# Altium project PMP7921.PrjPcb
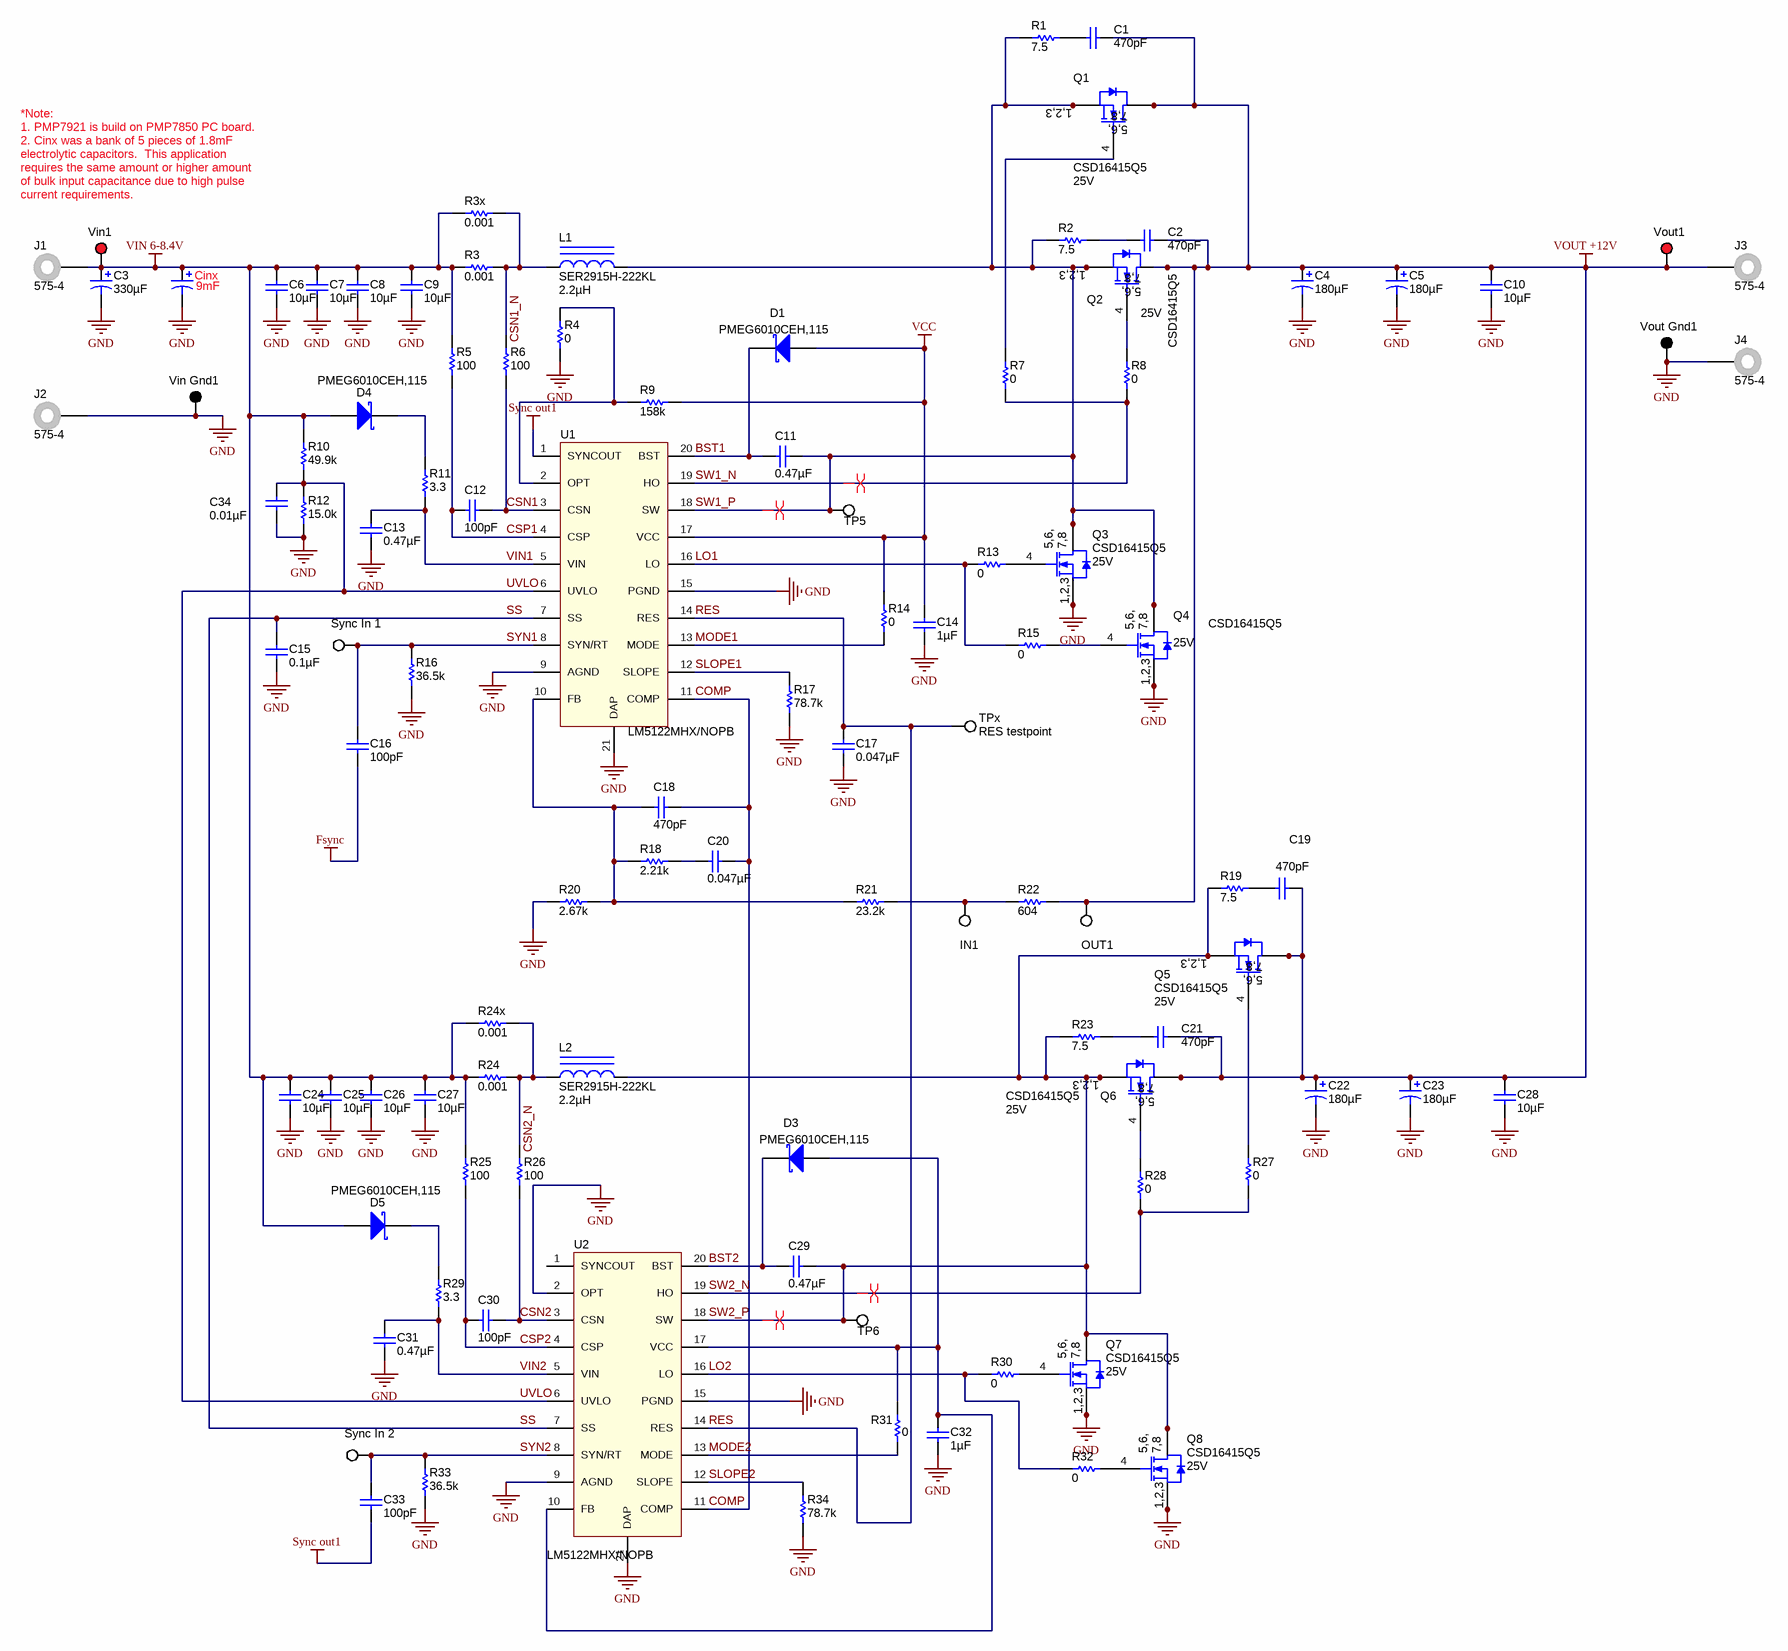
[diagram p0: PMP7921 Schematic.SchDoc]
TID: PMP7921; TechSupport: http://www.ti.com/support; SCH_Rev: 1; PRJ_Title: LM5122 Dual Phase Boost; PRJ_Number: PMP7921; PRJ_Engineer: Hrag Kasparian; PRJ_Customer: Public Release; PCB_Rev: B; PCB_Layout: Hrag Kasparian; EVM_Orderable: N/A; CopyrightYear: 2015
2 sheets, 110 parts. Net scope: global (net labels, ports and power ports of the same name join across sheets).
Board file: PMP7850 REVB.PcbDoc
Sheets:
  PMP7921 Schematic.SchDoc
  PMP7921_Hardware.SchDoc

## Sheet PMP7921 Schematic.SchDoc
size 558 x 431 mm; DocumentNumber: 1; SheetNumber: 1; SheetTotal: 2; PageSetup: Record=PageOptions¦CenterHorizontal=True¦CenterVertical=True¦PrintScale=0.70¦XCorrection=1.00¦YCorrection=1.00¦PrintKind=1¦BorderSize=5000000¦LeftOffset=0¦BottomOffset=0¦Orientation=2¦PaperLength=1000¦PaperWidth=1000¦Scale=100¦PaperSource=15¦PrintQuality=600¦MediaType=1¦DitherType=10¦PaperKind=11x17¦PrintScaleMode=1

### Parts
C1  ValueDisplayed: 470pF  [0805_HV]  (hidden comment: GRM2165C2A471JA01D)
C2  ValueDisplayed: 470pF  [0805_HV]  (hidden comment: GRM2165C2A471JA01D)
C3  ValueDisplayed: 330µF  [SVPS_F8]  (hidden comment: 10SVPS330M)
C4  ValueDisplayed: 180µF  [SVP_F8]  (hidden comment: 16SVP180MX)
C5  ValueDisplayed: 180µF  [SVP_F8]  (hidden comment: 16SVP180MX)
C6  ValueDisplayed: 10µF  [1206]  (hidden comment: C3216X5R1C106M)
C7  ValueDisplayed: 10µF  [1206]  (hidden comment: C3216X5R1C106M)
C8  ValueDisplayed: 10µF  [1206]  (hidden comment: C3216X5R1C106M)
C9  ValueDisplayed: 10µF  [1206]  (hidden comment: C3216X5R1C106M)
C10  ValueDisplayed: 10µF  [1206]  (hidden comment: C3216X5R1C106M)
C11  ValueDisplayed: 0.47µF  [0603_HV]  (hidden comment: GRM188R71E474KA12D)
C12  ValueDisplayed: 100pF  [0603_HV]  (hidden comment: GRM1885C1H101JA01D)
C13  ValueDisplayed: 0.47µF  [0603_HV]  (hidden comment: GRM188R71E474KA12D)
C14  ValueDisplayed: 1µF  [0603_HV]  (hidden comment: GRM188R71E105KA12D)
C15  ValueDisplayed: 0.1µF  [0603_HV]  (hidden comment: GRM188R71E104KA01D)
C16  ValueDisplayed: 100pF  [0603_HV]  (hidden comment: GRM1885C1H101JA01D)
C17  ValueDisplayed: 0.047µF  [0603_HV]  (hidden comment: GRM188R71E473KA01D)
C18  ValueDisplayed: 470pF  [0603]  (hidden comment: 06035A471JAT2A)
C19  ValueDisplayed: 470pF  [0805_HV]  (hidden comment: GRM2165C2A471JA01D)
C20  ValueDisplayed: 0.047µF  [0603]  (hidden comment: 06033C473JAT2A)
C21  ValueDisplayed: 470pF  [0805_HV]  (hidden comment: GRM2165C2A471JA01D)
C22  ValueDisplayed: 180µF  [SVP_F8]  (hidden comment: 16SVP180MX)
C23  ValueDisplayed: 180µF  [SVP_F8]  (hidden comment: 16SVP180MX)
C24  ValueDisplayed: 10µF  [1206]  (hidden comment: C3216X5R1C106M)
C25  ValueDisplayed: 10µF  [1206]  (hidden comment: C3216X5R1C106M)
C26  ValueDisplayed: 10µF  [1206]  (hidden comment: C3216X5R1C106M)
C27  ValueDisplayed: 10µF  [1206]  (hidden comment: C3216X5R1C106M)
C28  ValueDisplayed: 10µF  [1206]  (hidden comment: C3216X5R1C106M)
C29  ValueDisplayed: 0.47µF  [0603_HV]  (hidden comment: GRM188R71E474KA12D)
C30  ValueDisplayed: 100pF  [0603_HV]  (hidden comment: GRM1885C1H101JA01D)
C31  ValueDisplayed: 0.47µF  [0603_HV]  (hidden comment: GRM188R71E474KA12D)
C32  ValueDisplayed: 1µF  [0603_HV]  (hidden comment: GRM188R71E105KA12D)
C33  ValueDisplayed: 100pF  [0603_HV]  (hidden comment: GRM1885C1H101JA01D)
C34  ValueDisplayed: 0.01µF  [0603_HV]  (hidden comment: GRM188R71C103KA01D)
Cinx  9mF  [TBD]
D1  PMEG6010CEH,115  [SOD-123F]
D3  PMEG6010CEH,115  [SOD-123F]
D4  PMEG6010CEH,115  [SOD-123F]
D5  PMEG6010CEH,115  [SOD-123F]
IN1  5002  [Keystone5002]  (value not drawn)
J1  575-4  [Keystone_575-4]
J2  575-4  [Keystone_575-4]
J3  575-4  [Keystone_575-4]
J4  575-4  [Keystone_575-4]
L1  SER2915H-222KL  ValueDisplayed: 2.2µH  [SER2915]
L2  SER2915H-222KL  ValueDisplayed: 2.2µH  [SER2915]
OUT1  5002  [Keystone5002]  (value not drawn)
Q1  CSD16415Q5  value 25V  [Q5A WITH VIAS]
Q2  CSD16415Q5  value 25V  [Q5A WITH VIAS]
Q3  CSD16415Q5  value 25V  [Q5A WITH VIAS]
Q4  CSD16415Q5  value 25V  [Q5A WITH VIAS]
Q5  CSD16415Q5  value 25V  [Q5A WITH VIAS]
Q6  CSD16415Q5  value 25V  [Q5A WITH VIAS]
Q7  CSD16415Q5  value 25V  [Q5A WITH VIAS]
Q8  CSD16415Q5  value 25V  [Q5A WITH VIAS]
R1  value 7.5  [2010M]  (hidden comment: ERJ-12ZYJ7R5U)
R2  value 7.5  [2010M]  (hidden comment: ERJ-12ZYJ7R5U)
R3  value 0.001  [2512M]  (hidden comment: ERJ-M1WTF1M0U)
R3x  value 0.001  [2512M]  (hidden comment: ERJ-M1WTF1M0U)
R4  value 0  [0603_HV]  (hidden comment: ERJ-3GEY0R00V)
R5  value 100  [0603_HV]  (hidden comment: CRCW0603100RFKEA)
R6  value 100  [0603_HV]  (hidden comment: CRCW0603100RFKEA)
R7  value 0  [0603_HV]  (hidden comment: ERJ-3GEY0R00V)
R8  value 0  [0603_HV]  (hidden comment: ERJ-3GEY0R00V)
R9  value 158k  [0603_HV]  (hidden comment: CRCW0603158KFKEA)
R10  value 49.9k  [0603_HV]  (hidden comment: CRCW060349K9FKEA)
R11  value 3.3  [0603_HV]  (hidden comment: CRCW06033R30JNEA)
R12  value 15.0k  [0603_HV]  (hidden comment: RC0603FR-0715KL)
R13  value 0  [0603_HV]  (hidden comment: ERJ-3GEY0R00V)
R14  value 0  [0603_HV]  (hidden comment: ERJ-3GEY0R00V)
R15  value 0  [0603_HV]  (hidden comment: ERJ-3GEY0R00V)
R16  value 36.5k  [0603]  (hidden comment: CRCW060336K5FKEA)
R17  value 78.7k  [0603]  (hidden comment: CRCW060378K7FKEA)
R18  value 2.21k  [0603]  (hidden comment: CRCW06032K21FKEA)
R19  value 7.5  [2010M]  (hidden comment: ERJ-12ZYJ7R5U)
R20  value 2.67k  [0603_HV]  (hidden comment: CRCW06032K67FKEA)
R21  value 23.2k  [0603]  (hidden comment: CRCW060323K2FKEA)
R22  value 604  [0805_HV]  (hidden comment: CRCW0805604RFKEA)
R23  value 7.5  [2010M]  (hidden comment: ERJ-12ZYJ7R5U)
R24  value 0.001  [2512M]  (hidden comment: ERJ-M1WTF1M0U)
R24x  value 0.001  [2512M]  (hidden comment: ERJ-M1WTF1M0U)
R25  value 100  [0603_HV]  (hidden comment: CRCW0603100RFKEA)
R26  value 100  [0603_HV]  (hidden comment: CRCW0603100RFKEA)
R27  value 0  [0603_HV]  (hidden comment: ERJ-3GEY0R00V)
R28  value 0  [0603_HV]  (hidden comment: ERJ-3GEY0R00V)
R29  value 3.3  [0603_HV]  (hidden comment: CRCW06033R30JNEA)
R30  value 0  [0603_HV]  (hidden comment: ERJ-3GEY0R00V)
R31  value 0  [0603_HV]  (hidden comment: ERJ-3GEY0R00V)
R32  value 0  [0603_HV]  (hidden comment: ERJ-3GEY0R00V)
R33  value 36.5k  [0603]  (hidden comment: CRCW060336K5FKEA)
R34  value 78.7k  [0603]  (hidden comment: CRCW060378K7FKEA)
Sync_In_1  5002  [Keystone5002]  (value not drawn)
Sync_In_2  5002  [Keystone5002]  (value not drawn)
TP5  5002  [Keystone5002]  (value not drawn)
TP6  5002  [Keystone5002]  (value not drawn)
TPx  RES testpoint  [Keystone5002]
U1  LM5122MHX/NOPB  [MXA20A_L - 10milVia]
U2  LM5122MHX/NOPB  [MXA20A_L - 10milVia]
Vin1  5000  [Keystone5000]  (value not drawn)
Vin_Gnd1  5001  [Keystone5001]  (value not drawn)
Vout1  5000  [Keystone5000]  (value not drawn)
Vout_Gnd1  5001  [Keystone5001]  (value not drawn)

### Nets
Fsync: C16.1
GND: C3.2(-) C4.2(-) C5.2(-) C6.2 C7.2 C8.2 C9.2 C10.2 C13.2 C14.2 C15.2 C17.2 C22.2(-) C23.2(-) C24.2 C25.2 C26.2 C27.2 C28.2 C31.2 C32.2 C34.2 Cinx.2(-) J2.1 J4.1 Q3.1(S) Q3.2(S) Q3.3(S) Q4.1(S) Q4.2(S) Q4.3(S) Q7.1(S) Q7.2(S) Q7.3(S) Q8.1(S) Q8.2(S) Q8.3(S) R4.1 R12.1 R16.1 R17.1 R20.2 R33.1 R34.1 U1.9(AGND) U1.15(PGND) U1.21(DAP) U2.2(OPT) U2.9(AGND) U2.15(PGND) U2.21(DAP) Vin_Gnd1.1 Vout_Gnd1.1
Sync out1: C33.1 U1.1(SYNCOUT)
VCC: C14.1 D1.2(A) R9.2 R14.2 U1.17(VCC)
VIN 6-8.4V: C3.1(+) C6.1 C7.1 C8.1 C9.1 C24.1 C25.1 C26.1 C27.1 Cinx.1(+) D4.2(A) D5.2(A) J1.1 R3.1 R3x.1 R5.2 R10.2 R24.1 R24x.1 R25.2 Vin1.1
VOUT +12V: C1.1 C2.1 C4.1(+) C5.1(+) C10.1 C19.1 C21.1 C22.1(+) C23.1(+) C28.1 J3.1 OUT1.1 Q1.5(D) Q1.6(D) Q1.7(D) Q1.8(D) Q1.9(D) Q2.5(D) Q2.6(D) Q2.7(D) Q2.8(D) Q2.9(D) Q5.5(D) Q5.6(D) Q5.7(D) Q5.8(D) Q5.9(D) Q6.5(D) Q6.6(D) Q6.7(D) Q6.8(D) Q6.9(D) R22.1 Vout1.1
BST1: C11.2 D1.1(K) U1.20(BST)
BST2: C29.2 D3.1(K) U2.20(BST)
COMP: C18.2 C20.2 U1.11(COMP) U2.11(COMP)
CSN1: C12.1 R6.1 U1.3(CSN)
CSN1_N: L1.1 R3.2 R3x.2 R6.2
CSN2: C30.1 R26.1 U2.3(CSN)
CSN2_N: L2.1 R24.2 R24x.2 R26.2
CSP1: C12.2 R5.1 U1.4(CSP)
CSP2: C30.2 R25.1 U2.4(CSP)
LO1: R13.2 R15.2 U1.16(LO)
LO2: R30.2 R32.2 U2.16(LO)
MODE1: R14.1 U1.13(MODE)
MODE2: R31.1 U2.13(MODE)
RES: C17.1 TPx.1 U1.14(RES) U2.14(RES)
SLOPE1: R17.2 U1.12(SLOPE)
SLOPE2: R34.2 U2.12(SLOPE)
SS: C15.1 U1.7(SS) U2.7(SS)
SW1_N: R7.2 R8.2 U1.19(HO)
SW1_P: C11.1 L1.2 Q1.1(S) Q1.2(S) Q1.3(S) Q2.1(S) Q2.2(S) Q2.3(S) Q3.5(D) Q3.6(D) Q3.7(D) Q3.8(D) Q3.9(D) Q4.5(D) Q4.6(D) Q4.7(D) Q4.8(D) Q4.9(D) R1.2 R2.2 TP5.1 U1.18(SW)
SW2_N: R27.2 R28.2 U2.19(HO)
SW2_P: C29.1 L2.2 Q5.1(S) Q5.2(S) Q5.3(S) Q6.1(S) Q6.2(S) Q6.3(S) Q7.5(D) Q7.6(D) Q7.7(D) Q7.8(D) Q7.9(D) Q8.5(D) Q8.6(D) Q8.7(D) Q8.8(D) Q8.9(D) R19.2 R23.2 TP6.1 U2.18(SW)
SYN1: C16.2 R16.2 Sync_In_1.1 U1.8(SYN/RT)
SYN2: C33.2 R33.2 Sync_In_2.1 U2.8(SYN/RT)
UVLO: C34.1 R10.1 R12.2 U1.6(UVLO) U2.6(UVLO)
VIN1: C13.1 R11.1 U1.5(VIN)
VIN2: C31.1 R29.1 U2.5(VIN)
NetC1_2: C1.2 R1.1
NetC2_2: C2.2 R2.1
NetC18_1: C18.1 R18.1 R20.1 R21.1 U1.10(FB)
NetC19_2: C19.2 R19.1
NetC20_1: C20.1 R18.2
NetC21_2: C21.2 R23.1
NetC32_1: C32.1 D3.2(A) R31.2 U2.10(FB) U2.17(VCC)
NetD4_1: D4.1(K) R11.2
NetD5_1: D5.1(K) R29.2
NetIN1_1: IN1.1 R21.2 R22.2
NetQ1_4: Q1.4(G) R7.1
NetQ2_4: Q2.4(G) R8.1
NetQ3_4: Q3.4(G) R13.1
NetQ4_4: Q4.4(G) R15.1
NetQ5_4: Q5.4(G) R27.1
NetQ6_4: Q6.4(G) R28.1
NetQ7_4: Q7.4(G) R30.1
NetQ8_4: Q8.4(G) R32.1
NetR4_2: R4.2 R9.1 U1.2(OPT)

Not connected (* = marked no-connect by the designer): U2 1(SYNCOUT)

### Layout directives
differential pair: SW1_N, SW1_P, SW2_N, SW2_P

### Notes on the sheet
- *Note:
  1. PMP7921 is build on PMP7850 PC board.
  2. Cinx was a bank of 5 pieces of 1.8mF electrolytic capacitors.  This application requires the same amount or higher amount of bulk input capacitance due to high pulse current requirements.

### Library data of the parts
C1 C2 C19 C21 = GRM2165C2A471JA01D: CAP, CERM, 470pF, 100V, +/-5%, C0G/NP0, 0805; Manufacturer: MuRata; Polarized: N; CompType: Capacitor; U/M: EA; Cap_F: 0.00000000047; Tolerance_%: 5; VDC_V: 100; TaMin_C: -55; TaMax_C: 125; Cap_Case: 0805
C3 = 10SVPS330M: CAP, AL, 330uF, 10V, +/-20%, SMD; Manufacturer: Panasonic; Polarized: Y; CompType: Capacitor; U/M: EA; Cap_F: 0.00033; Tolerance_%: 20; VDC_V: 25; Value2: 25V; IRMS_A: 0.6; TaMin_C: -55; TaMax_C: 105; Cap_Case: HA0
C4 C5 C22 C23 = 16SVP180MX: CAP, AL, 180uF, 16V, +/-20%, SMD; Manufacturer: Sanyo; Polarized: Y; CompType: Capacitor; U/M: EA; Cap_F: 0.00033; Tolerance_%: 20; VDC_V: 16; IRMS_A: 0.6; TaMin_C: -55; TaMax_C: 105; Cap_Case: HA0
C6-C10 C24-C28 = C3216X5R1C106M: CAP, CERM, 10uF, 16V, +/-20%, X5R, 1206; Manufacturer: TDK; Polarized: N; CompType: Capacitor; U/M: EA; Cap_F: 0.00001; Tolerance_%: 20; ESR_Ohm: 0.0046; Value1: 0.0046 ohm; VDC_V: 16; IRMS_A: 2.7; TaMin_C: -55; TaMax_C: 85
C11 C13 C29 C31 = GRM188R71E474KA12D: CAP, CERM, 0.47uF, 25V, +/-10%, X7R, 0603; Manufacturer: MuRata; Polarized: N; CompType: Capacitor; U/M: EA; Cap_F: 0.00000047; Tolerance_%: 10; VDC_V: 25; TaMin_C: -55; TaMax_C: 125; Cap_Case: 0603
C12 C16 C30 C33 = GRM1885C1H101JA01D: CAP, CERM, 100pF, 50V, +/-5%, C0G/NP0, 0603; Manufacturer: MuRata; Polarized: N; CompType: Capacitor; U/M: EA; Cap_F: 0.0000000001; Tolerance_%: 5; VDC_V: 50; TaMin_C: -55; TaMax_C: 125; Cap_Case: 0603
C14 C32 = GRM188R71E105KA12D: CAP, CERM, 1uF, 25V, +/-10%, X7R, 0603; Manufacturer: MuRata; Polarized: N; CompType: Capacitor; U/M: EA; Cap_F: 0.000001; Tolerance_%: 10; VDC_V: 25; TaMin_C: -55; TaMax_C: 125; Cap_Case: 0603
C15 = GRM188R71E104KA01D: CAP, CERM, 0.1uF, 25V, +/-10%, X7R, 0603; Manufacturer: MuRata; Polarized: N; CompType: Capacitor; U/M: EA; Cap_F: 0.0000001; Tolerance_%: 10; VDC_V: 25; TaMin_C: -55; TaMax_C: 125; Cap_Case: 0603
C17 = GRM188R71E473KA01D: CAP, CERM, 0.047uF, 25V, +/-10%, X7R, 0603; Manufacturer: MuRata; Polarized: N; CompType: Capacitor; U/M: EA; Cap_F: 0.000000047; Tolerance_%: 10; VDC_V: 25; TaMin_C: -55; TaMax_C: 125; Cap_Case: 0603
C18 = 06035A471JAT2A: CAP, CERM, 470pF, 50V, +/-5%, C0G/NP0, 0603; Manufacturer: AVX; Polarized: N; CompType: Capacitor; U/M: EA; Cap_F: 0.00000000047; Tolerance_%: 5; ESR_Ohm: 0.063; Value1: 0.063 ohm; VDC_V: 50; TaMin_C: -55; TaMax_C: 125
C20 = 06033C473JAT2A: CAP, CERM, 0.047uF, 25V, +/-5%, X7R, 0603; Manufacturer: AVX; Polarized: N; CompType: Capacitor; U/M: EA; Cap_F: 0.000000047; Tolerance_%: 5; ESR_Ohm: 0.052; Value1: 0.052 ohm; VDC_V: 25; TaMin_C: -55; TaMax_C: 125
C34 = GRM188R71C103KA01D: CAP, CERM, 0.01uF, 16V, +/-10%, X7R, 0603; Manufacturer: MuRata; Polarized: N; CompType: Capacitor; U/M: EA; Cap_F: 0.00000001; Tolerance_%: 10; VDC_V: 16; TaMin_C: -55; TaMax_C: 125; Cap_Case: 0603
Cinx = Capacitor_Polarized: CAP, Aluminum, 1800uF, 16V, [TH]; Manufacturer: SUNCON; PartNumber: 16ME1800AX; Polarized: Y; Value: 1.8mF; U/M: EA
D1 D3-D5 = PMEG6010CEH,115: Diode, Schottky, 60V, 1A, SOD-123F; Manufacturer: NXP Semiconductor; U/M: EA; Vf_V: 0.57; Io_A: 1; Vr_V: 60; TJmax_C: 150; Value: 0.57V
IN1 OUT1 Sync_In_1 Sync_In_2 TP5 TP6 TPx = 5002: Test Point, TH, Miniature, White; Manufacturer: Keystone; Alternate Manufacturer: Any; Alternate PartNumber: Equivalent; CompType: Test Point Loop; U/M: EA
J1-J4 = 575-4: Standard Banana Jack, Uninsulated, 5.5mm; Manufacturer: Keystone; Alternate Manufacturer: Any; Alternate PartNumber: Equivalent; CompType: Connector; U/M: EA
L1 L2 = SER2915H-222KL: Inductor, Shielded E Core, Ferrite, 2.2uH, 30A, 0.00186 ohm, SMD; Manufacturer: Coilcraft; Ind_H: 2.2E-6; Imax_A: 30; Irms: 30A @ 40C rise; Isat: 100A @ 30% inductance drop; U/M: EA
Q1-Q8 = CSD16415Q5: MOSFET N-CH 25V 8SON; Manufacturer: Texas Instruments; U/M: EA; ChType: N; VdsMax_V: 25; Value1: 0.0015 ohm; Rdson45_Ohm: 0.0033; Value2: 21 nC; QgTyp_nC: 19; Vgs_V: 12; IdsMax_A: 100
R1 R2 R19 R23 = ERJ-12ZYJ7R5U: RESISTOR 7.5 OHM 3/4W 5% 2010; Manufacturer: Panasonic; Value_Code: 7R50; Tolerance_%: 5; Power_W: 1; Value2: 1W; VDC_V: 3; TempCo: -100 /+600 ppm/C; EIA_Code: E24; U/M: EA
R3 R3x R24 R24x = ERJ-M1WTF1M0U: RES, 0.001 ohm, 1%, 1W, 2512; Manufacturer: Panasonic; CompType: Resistor; Value_Code: R001; Tolerance_%: 1; TempCo: ppm/C; EIA_Code: E96; U/M: EA
R4 R7 R8 R13-R15 R27 R28 R30-R32 = ERJ-3GEY0R00V: RES, 0 ohm, 5%, 0.1W, 0603; Manufacturer: Panasonic; CompType: Resistor; Value_Code: 0000; Tolerance_%: 5; Power_W: 0.1; VDC_V: 50; TempCo: 600 ppm/C; EIA_Code: E24; U/M: EA
R5 R6 R25 R26 = CRCW0603100RFKEA: RES, 100 ohm, 1%, 0.1W, 0603; Manufacturer: Vishay-Dale; CompType: Resistor; Value_Code: 100R; Tolerance_%: 1; Power_W: 0.1; VDC_V: 75; TempCo: 100 ppm/C; EIA_Code: E96; U/M: EA
R9 = CRCW0603158KFKEA: RES, 158k ohm, 1%, 0.1W, 0603; Manufacturer: Vishay-Dale; CompType: Resistor; Res_ohm: 158000; Tolerance_%: 1; Power_W: 0.1; VDC_V: 75; TempCo: 100 ppm/C; EIA_Code: E96; U/M: EA
R10 = CRCW060349K9FKEA: RES, 49.9k ohm, 1%, 0.1W, 0603; Manufacturer: Vishay-Dale; CompType: Resistor; Res_ohm: 49900; Value_Code: 49k9; Tolerance_%: 1; Power_W: 0.1; VDC_V: 75; TempCo: 100 ppm/C; EIA_Code: E96; U/M: EA
R11 R29 = CRCW06033R30JNEA: RES, 3.3 ohm, 5%, 0.1W, 0603; Manufacturer: Vishay-Dale; CompType: Resistor; Value_Code: 3R30; Tolerance_%: 5; Power_W: 0.1; VDC_V: 75; TempCo: 200 ppm/C; EIA_Code: E24; U/M: EA
R12 = RC0603FR-0715KL: RES, 15.0k ohm, 1%, 0.1W, 0603; Manufacturer: Yageo America; CompType: Resistor; Res_ohm: 15000; Value_Code: 15k0; Tolerance_%: 1; Power_W: 0.1; VDC_V: 150; TempCo: 200 ppm/C; EIA_Code: E96; U/M: EA
R16 R33 = CRCW060336K5FKEA: RES, 36.5k ohm, 1%, 0.1W, 0603; Manufacturer: Vishay-Dale; CompType: Resistor; Res_ohm: 36500; Value_Code: 36k5; Tolerance_%: 1; Power_W: 0.1; VDC_V: 75; TempCo: 100 ppm/C; EIA_Code: E96; U/M: EA
R17 R34 = CRCW060378K7FKEA: RES, 78.7k ohm, 1%, 0.1W, 0603; Manufacturer: Vishay-Dale; CompType: Resistor; Res_ohm: 78700; Value_Code: 78k7; Tolerance_%: 1; Power_W: 0.1; VDC_V: 75; TempCo: 100 ppm/C; EIA_Code: E96; U/M: EA
R18 = CRCW06032K21FKEA: RES, 2.21k ohm, 1%, 0.1W, 0603; Manufacturer: Vishay-Dale; CompType: Resistor; Res_ohm: 2210; Value_Code: 2k21; Tolerance_%: 1; Power_W: 0.1; VDC_V: 75; TempCo: 100 ppm/C; EIA_Code: E96; U/M: EA
R20 = CRCW06032K67FKEA: RES, 2.67k ohm, 1%, 0.1W, 0603; Manufacturer: Vishay-Dale; CompType: Resistor; Res_ohm: 2670; Value_Code: 2k67; Tolerance_%: 1; Power_W: 0.1; VDC_V: 75; TempCo: 100 ppm/C; EIA_Code: E96; U/M: EA
R21 = CRCW060323K2FKEA: RES, 23.2k ohm, 1%, 0.1W, 0603; Manufacturer: Vishay-Dale; CompType: Resistor; Res_ohm: 23200; Value_Code: 23k2; Tolerance_%: 1; Power_W: 0.1; VDC_V: 75; TempCo: 100 ppm/C; EIA_Code: E96; U/M: EA
R22 = CRCW0805604RFKEA: RES, 604 ohm, 1%, 0.125W, 0805; Manufacturer: Vishay-Dale; CompType: Resistor; Value_Code: 604R; Tolerance_%: 1; Power_W: 0.125; VDC_V: 150; TempCo: 100 ppm/C; EIA_Code: E96; U/M: EA
U1 U2 = LM5122MHX/NOPB: Wide Input Synchronous Boost Controller with Multiple Phase Capability, PWP0020A; Manufacturer: Texas Instruments; Alternate PartNumber: LM5122MHE/NOPB; SymbolCreator: a0411947; CompType: IC; U/M: EA
Vin1 Vout1 = 5000: Test Point, TH, Miniature, Red; Manufacturer: Keystone; CompType: Test Point Loop; U/M: EA
Vin_Gnd1 Vout_Gnd1 = 5001: Test Point, TH, Miniature, Black; Manufacturer: Keystone; CompType: Test Point Loop; U/M: EA

## Sheet PMP7921_Hardware.SchDoc
size 431 x 279 mm; Date: Not shown in title block; ApprovedBy: Not shown in title block; CheckedBy: Not shown in title block; Author: Not shown in title block; CompanyName: Not shown in title block; Engineer: Not shown in title block; Organization: Not shown in title block; Address1: Not shown in title block; Address2: Not shown in title block; Address3: Not shown in title block; Address4: Not shown in title block; DocumentNumber: 2; Revision: Use project parameter SCH_Rev; SheetNumber: 2; SheetTotal: 2; PageSetup: Record=PageOptions¦CenterHorizontal=True¦CenterVertical=True¦PrintScale=1.00¦XCorrection=1.00¦YCorrection=1.00¦PrintKind=0¦BorderSize=5000000¦LeftOffset=0¦BottomOffset=0¦Orientation=2¦PaperLength=1000¦PaperWidth=1000¦Scale=100¦PaperSource=15¦PrintQuality=600¦MediaType=1¦DitherType=10¦PaperKind=Letter¦PrintScaleMode=1
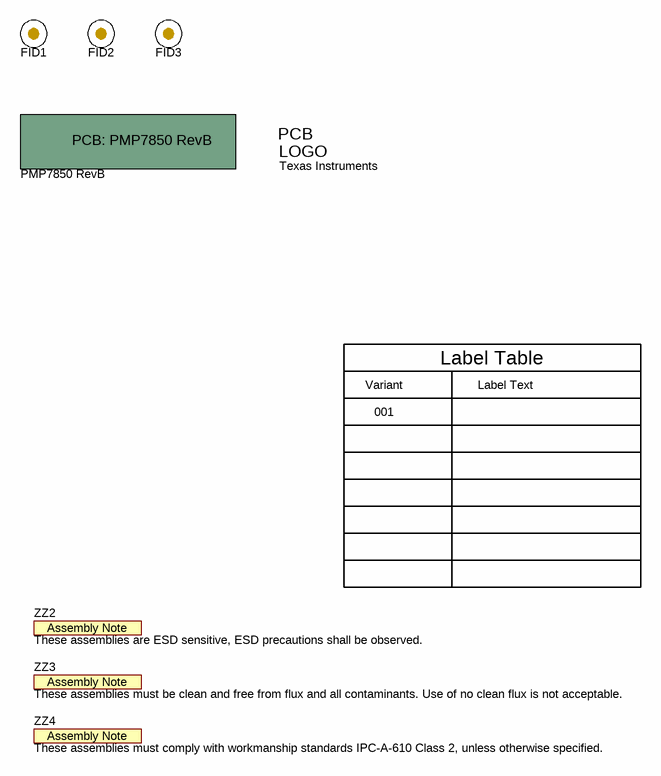
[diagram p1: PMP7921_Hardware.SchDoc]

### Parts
!PCB?  PMP7850 RevB  (mechanical)
FID1  Fiducial  [Fiducial10-20]  (value not drawn)
FID2  Fiducial  [Fiducial10-20]  (value not drawn)
FID3  Fiducial  [Fiducial10-20]  (value not drawn)
Logo1  Texas Instruments  [TI_Stacked_Overlay_Small]  (no BOM)
ZZ2  These assemblies are ESD sensitive, ESD precautions shall be observed.  [AssemblyNote]  (no BOM)
ZZ3  These assemblies must be clean and free from flux and all contaminants. Use of no clean flux is not acceptable.  [AssemblyNote]  (no BOM)
ZZ4  These assemblies must comply with workmanship standards IPC-A-610 Class 2, unless otherwise specified.  [AssemblyNote]  (no BOM)

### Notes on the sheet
- Variant
- Label Table
- Label Text
- 001

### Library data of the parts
!PCB? = PCB_OtherProject: Manufacturer: Any; SymbolCreator: a0412235; CompType: PCB; U/M: EA
FID1-FID3 = Fiducial: Fiducial mark.  There is nothing to buy or mount.; SymbolCreator: codlsc
Logo1 = TI_Logo: Texas Instrument Corporate Signature; SymbolCreator: codlsc
ZZ2-ZZ4 = AssemblyNote: SymbolCreator: codlsc

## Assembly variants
001: not fitted FID1 FID2 FID3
